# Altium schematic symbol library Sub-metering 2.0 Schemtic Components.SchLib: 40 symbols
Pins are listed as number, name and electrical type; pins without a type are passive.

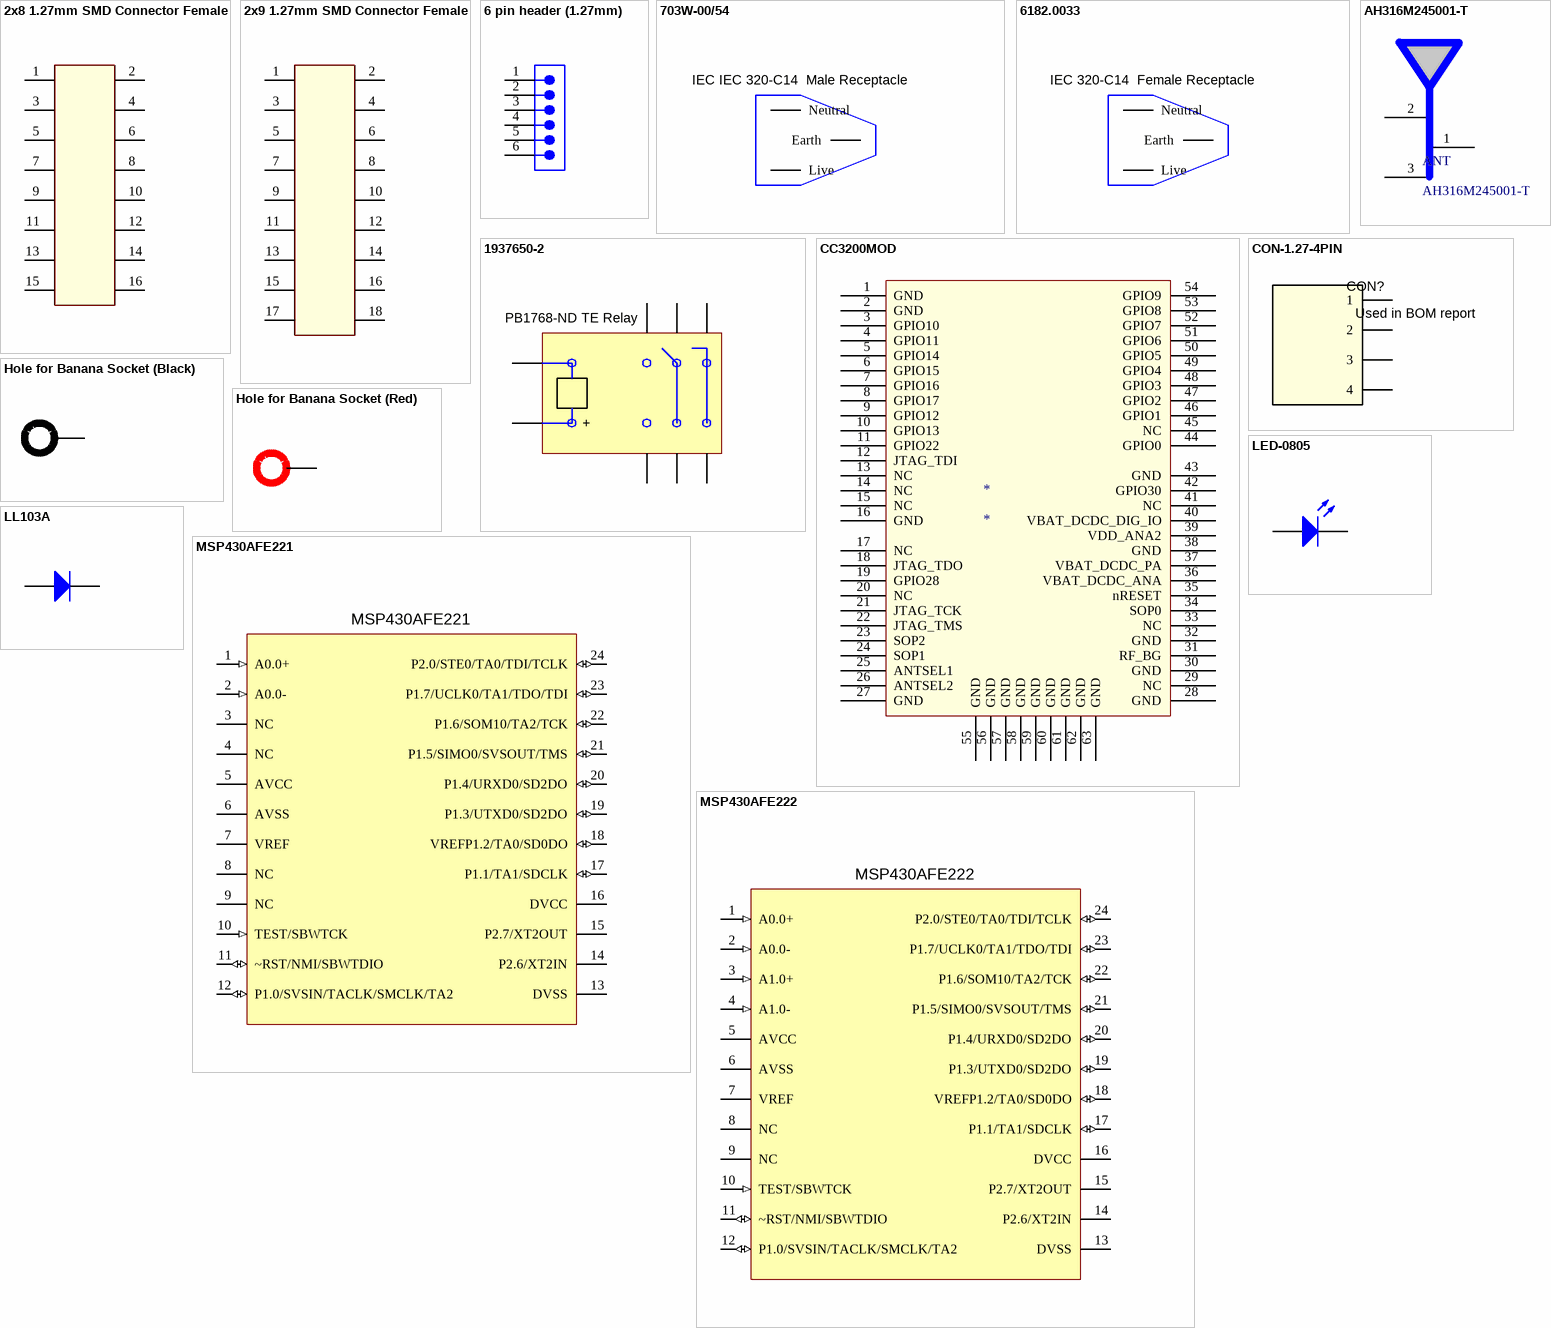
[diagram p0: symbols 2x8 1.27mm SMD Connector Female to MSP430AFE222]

## 2x8 1.27mm SMD Connector Female
designator U?, comment Used in BOM report
SymbolVersion: use current date i.e. 2008-05-20; SymbolCreator: Use LDAP id; CompType: Used in some BOM reports.  Useful for finding later.; U/M: EA, IN, or GM
footprint 2X8 1.27mm PITCH CONNECTOR FEMALE
pins: 1, 2, 3, 4, 5, 6, 7, 8, 9, 10, 11, 12, 13, 14, 15, 16

## 2x9 1.27mm SMD Connector Female
designator U?, comment Used in BOM report
SymbolVersion: use current date i.e. 2008-05-20; SymbolCreator: Use LDAP id; CompType: Used in some BOM reports.  Useful for finding later.; U/M: EA, IN, or GM
footprint 2X9 1.27mm PITCH CONNECTOR FEMALE
pins: 1, 2, 3, 4, 5, 6, 7, 8, 9, 10, 11, 12, 13, 14, 15, 16, 17, 18

## 6 pin header (1.27mm)
designator U?, comment Used in BOM report
SymbolVersion: use current date i.e. 2008-05-20; SymbolCreator: Use LDAP id; CompType: Used in some BOM reports.  Useful for finding later.; U/M: EA, IN, or GM
footprint 6-pin header (1.27mm) (6 pin header 1.27mm)
pins: 1, 2, 3, 4, 5, 6

## 703W-00/54
designator SOC?
CONN AC RECEPT 9MM R/A FLAT PCB; Manufacturer: Qualtek; SymbolVersion: use current date i.e. 2008-05-20; SymbolCreator: Use a-id; CompType: Used in some BOM reports.  Useful for finding later.; U/M: EA, IN, or GM; Connector Style: IEC 320-C14; Connector Type: Receptacle, Male Pins; Irms: 10A; Voltage: 250V; Number of Positions: 3; Fuse Drawer: Drawer Not Required
footprint 703W-00/54 (IEC 320-C14 , Receptacle, Male Pins)
pins: 1 Earth, 2 Neutral, 3 Live

## 6182.0033
designator SOC?
MODULE PWR OUTLET F SCREW-ON PCB; Manufacturer: Schurter Inc; SymbolVersion: use current date i.e. 2008-05-20; SymbolCreator: Use a-id; CompType: Used in some BOM reports.  Useful for finding later.; U/M: EA, IN, or GM; Connector Style: IEC 320-C13; Connector Type: Receptacle, Female Sockets; Irms: 15A; Voltage: 250V; Number of Positions: 3; Fuse Drawer: Drawer Not Required
footprint 486-1343-ND
pins: 1 Earth, 2 Neutral, 3 Live

## 1937650-2
designator REL?, comment RTX3-1AT-B005
RELAY GEN PURPOSE SPST 16A 5V; Manufacturer: TE Electronics; SymbolVersion: use current date i.e. 2008-05-20; SymbolCreator: Use a-id; CompType: Used in some BOM reports.  Useful for finding later.; U/M: EA, IN, or GM; Relay Type: General Purpose; Coil Type: Latching, Single Coil; Coil Current: 130mA; Coil Voltage: 5VDC; Contact Form: SPST-NO (1 Form A); Switching Voltage: 250VAC - Nom; Turn On Voltage (Max): 3.75 VDC; Coil Power: 650 mW; Coil Resistance: 38 Ohms
footprint TE RELAY TYPE A (TE Relay type A footprint)
pins: 1, 2, 3, 4, 5, 6, 7, 8

## AH316M245001-T
designator ANT
Manufacturer: Taiyo Yuden; Value: 2.45-GHz Ant
footprint AH316M
pins: 1, 2, 3

## CC3200MOD
designator *
footprint CC3200MOD
pins: 1 GND, 2 GND, 3 GPIO10, 4 GPIO11, 5 GPIO14, 6 GPIO15, 7 GPIO16, 8 GPIO17, 9 GPIO12, 10 GPIO13, 11 GPIO22, 12 JTAG_TDI, 13 NC, 14 NC, 15 NC, 16 GND, 17 NC, 18 JTAG_TDO, 19 GPIO28, 20 NC, 21 JTAG_TCK, 22 JTAG_TMS, 23 SOP2, 24 SOP1, 25 ANTSEL1, 26 ANTSEL2, 27 GND, 28 GND, 29 NC, 30 GND, 31 RF_BG, 32 GND, 33 NC, 34 SOP0, 35 nRESET, 36 VBAT_DCDC_ANA, 37 VBAT_DCDC_PA, 38 GND, 39 VDD_ANA2, 40 VBAT_DCDC_DIG_IO, 41 NC, 42 GPIO30, 43 GND, 44 GPIO0, 45 NC, 46 GPIO1, 47 GPIO2, 48 GPIO3, 49 GPIO4, 50 GPIO5, 51 GPIO6, 52 GPIO7, 53 GPIO8, 54 GPIO9, 55 GND, 56 GND, 57 GND, 58 GND, 59 GND, 60 GND, 61 GND, 62 GND, 63 GND

## CON-1.27-4PIN
designator CON?, comment Used in BOM report
SymbolVersion: use current date i.e. 2008-05-20; SymbolCreator: Use a-id; CompType: Used in some BOM reports.  Useful for finding later.; U/M: EA, IN, or GM
footprint CON-1.27-4PIN (1.27mm connector 4 pin)
pins: 1, 2, 3, 4

## Hole for Banana Socket (Black)
designator J?, comment Used in BOM report
SymbolVersion: use current date i.e. 2008-05-20; SymbolCreator: Use LDAP id; CompType: Used in some BOM reports.  Useful for finding later.; U/M: EA, IN, or GM
footprint Hole for Banana Socket
pins: 1

## Hole for Banana Socket (Red)
designator J?, comment Used in BOM report
SymbolVersion: use current date i.e. 2008-05-20; SymbolCreator: Use LDAP id; CompType: Used in some BOM reports.  Useful for finding later.; U/M: EA, IN, or GM
footprint Hole for Banana Socket
pins: 1

## LED-0805
designator U?, comment Used in BOM report
SymbolVersion: use current date i.e. 2008-05-20; SymbolCreator: Use LDAP id; CompType: Used in some BOM reports.  Useful for finding later.; U/M: EA, IN, or GM
footprint 0805-LED
pins: 1 A, 2 K

## LL103A
designator D?
Manufacturer: Used in BOM report; SymbolVersion: use current date i.e. 2008-05-20; SymbolCreator: Use LDAP id; CompType: Used in some BOM reports.  Useful for finding later.; U/M: EA, IN, or GM
footprint SOD-80 (VISHAY)
pins: 1 A, 2 K

## MSP430AFE221
designator U?
Manufacturer: Texas Instruments; SymbolVersion: use current date i.e. 2008-05-20; SymbolCreator: Use LDAP id; CompType: Used in some BOM reports.  Useful for finding later.; U/M: EA, IN, or GM
footprint R-PDSO-G24
footprint TSSOP-24 (TSSOP-24 (IPW))
pins: 1 A0.0+ (in), 2 A0.0- (in), 3 NC, 4 NC, 5 AVCC (power), 6 AVSS (power), 7 VREF, 8 NC, 9 NC, 10 TEST/SBWTCK (in), 11 ~RST/NMI/SBWTDIO (io), 12 P1.0/SVSIN/TACLK/SMCLK/TA2 (io), 13 DVSS (power), 14 P2.6/XT2IN, 15 P2.7/XT2OUT, 16 DVCC (power), 17 P1.1/TA1/SDCLK (io), 18 VREFP1.2/TA0/SD0DO (io), 19 P1.3/UTXD0/SD2DO (io), 20 P1.4/URXD0/SD2DO (io), 21 P1.5/SIMO0/SVSOUT/TMS (io), 22 P1.6/SOM10/TA2/TCK (io), 23 P1.7/UCLK0/TA1/TDO/TDI (io), 24 P2.0/STE0/TA0/TDI/TCLK (io)

## MSP430AFE222
designator U?
Manufacturer: Texas Instruments; SymbolVersion: use current date i.e. 2008-05-20; SymbolCreator: Use LDAP id; CompType: Used in some BOM reports.  Useful for finding later.; U/M: EA, IN, or GM
footprint R-PDSO-G24
footprint TSSOP-24 (TSSOP-24 (IPW))
pins: 1 A0.0+ (in), 2 A0.0- (in), 3 A1.0+ (in), 4 A1.0- (in), 5 AVCC (power), 6 AVSS (power), 7 VREF, 8 NC, 9 NC, 10 TEST/SBWTCK (in), 11 ~RST/NMI/SBWTDIO (io), 12 P1.0/SVSIN/TACLK/SMCLK/TA2 (io), 13 DVSS (power), 14 P2.6/XT2IN, 15 P2.7/XT2OUT, 16 DVCC (power), 17 P1.1/TA1/SDCLK (io), 18 VREFP1.2/TA0/SD0DO (io), 19 P1.3/UTXD0/SD2DO (io), 20 P1.4/URXD0/SD2DO (io), 21 P1.5/SIMO0/SVSOUT/TMS (io), 22 P1.6/SOM10/TA2/TCK (io), 23 P1.7/UCLK0/TA1/TDO/TDI (io), 24 P2.0/STE0/TA0/TDI/TCLK (io)

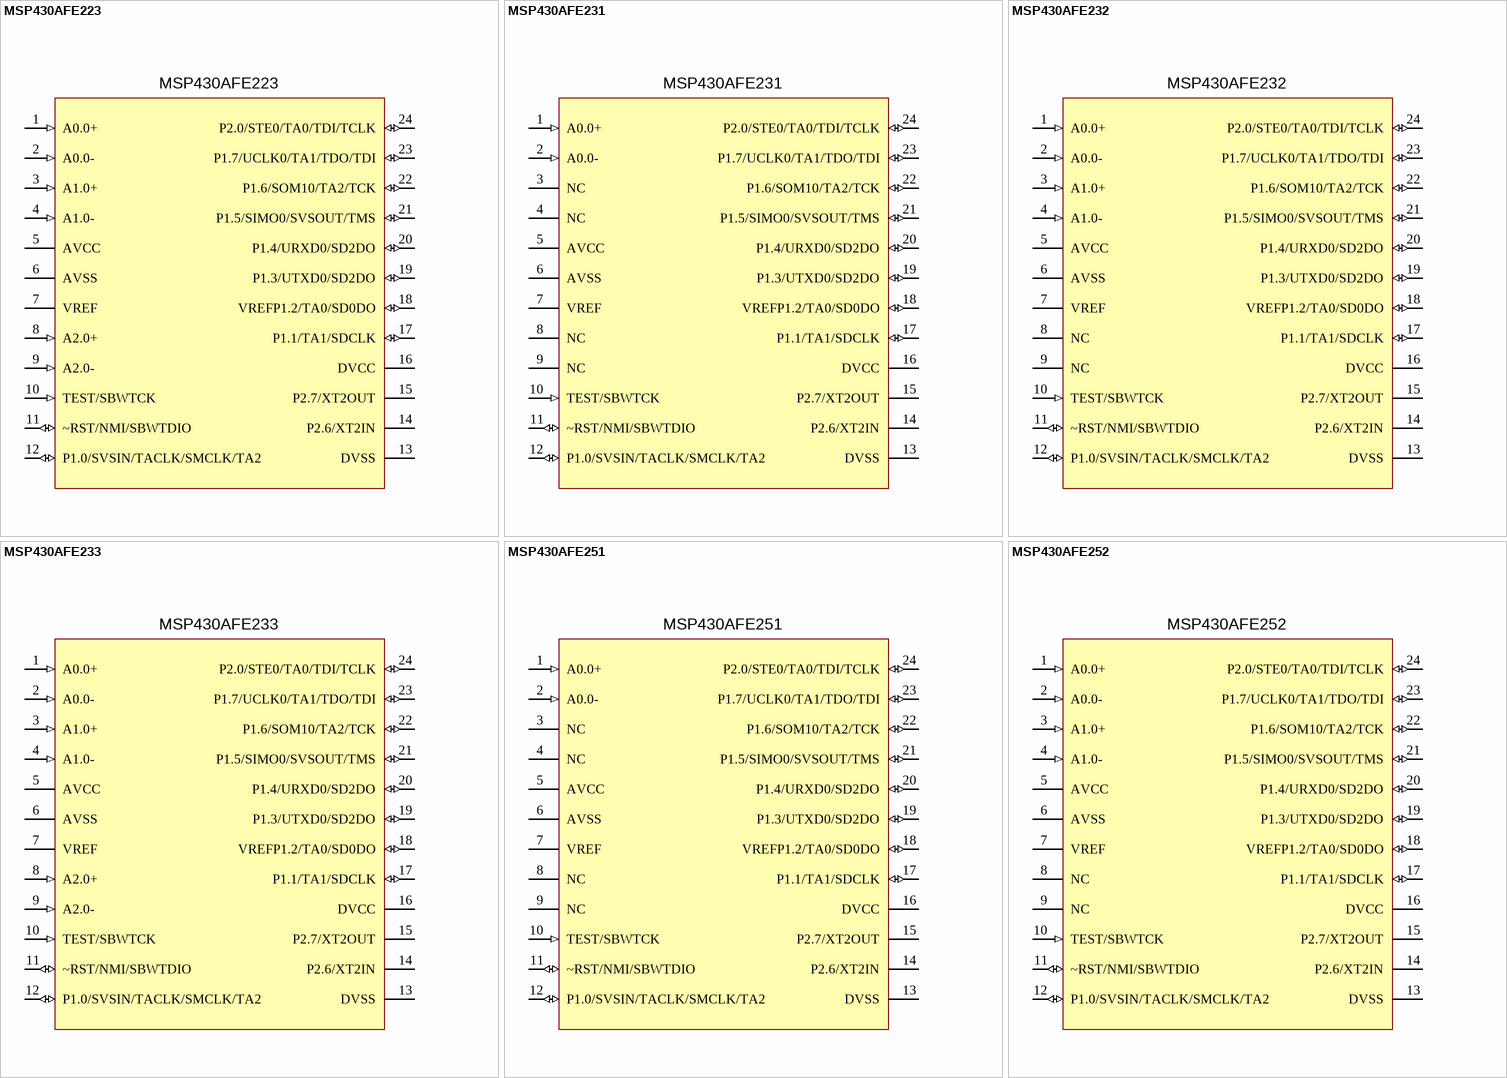
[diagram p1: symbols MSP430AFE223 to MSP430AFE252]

## MSP430AFE223
designator U?
Manufacturer: Texas Instruments; SymbolVersion: use current date i.e. 2008-05-20; SymbolCreator: Use LDAP id; CompType: Used in some BOM reports.  Useful for finding later.; U/M: EA, IN, or GM
footprint R-PDSO-G24
footprint TSSOP-24 (TSSOP-24 (IPW))
pins: 1 A0.0+ (in), 2 A0.0- (in), 3 A1.0+ (in), 4 A1.0- (in), 5 AVCC (power), 6 AVSS (power), 7 VREF, 8 A2.0+ (in), 9 A2.0- (in), 10 TEST/SBWTCK (in), 11 ~RST/NMI/SBWTDIO (io), 12 P1.0/SVSIN/TACLK/SMCLK/TA2 (io), 13 DVSS (power), 14 P2.6/XT2IN, 15 P2.7/XT2OUT, 16 DVCC (power), 17 P1.1/TA1/SDCLK (io), 18 VREFP1.2/TA0/SD0DO (io), 19 P1.3/UTXD0/SD2DO (io), 20 P1.4/URXD0/SD2DO (io), 21 P1.5/SIMO0/SVSOUT/TMS (io), 22 P1.6/SOM10/TA2/TCK (io), 23 P1.7/UCLK0/TA1/TDO/TDI (io), 24 P2.0/STE0/TA0/TDI/TCLK (io)

## MSP430AFE231
designator U?
Manufacturer: Texas Instruments; SymbolVersion: use current date i.e. 2008-05-20; SymbolCreator: Use LDAP id; CompType: Used in some BOM reports.  Useful for finding later.; U/M: EA, IN, or GM
footprint R-PDSO-G24
footprint TSSOP-24 (TSSOP-24 (IPW))
pins: 1 A0.0+ (in), 2 A0.0- (in), 3 NC, 4 NC, 5 AVCC (power), 6 AVSS (power), 7 VREF, 8 NC, 9 NC, 10 TEST/SBWTCK (in), 11 ~RST/NMI/SBWTDIO (io), 12 P1.0/SVSIN/TACLK/SMCLK/TA2 (io), 13 DVSS (power), 14 P2.6/XT2IN, 15 P2.7/XT2OUT, 16 DVCC (power), 17 P1.1/TA1/SDCLK (io), 18 VREFP1.2/TA0/SD0DO (io), 19 P1.3/UTXD0/SD2DO (io), 20 P1.4/URXD0/SD2DO (io), 21 P1.5/SIMO0/SVSOUT/TMS (io), 22 P1.6/SOM10/TA2/TCK (io), 23 P1.7/UCLK0/TA1/TDO/TDI (io), 24 P2.0/STE0/TA0/TDI/TCLK (io)

## MSP430AFE232
designator U?
Manufacturer: Texas Instruments; SymbolVersion: use current date i.e. 2008-05-20; SymbolCreator: Use LDAP id; CompType: Used in some BOM reports.  Useful for finding later.; U/M: EA, IN, or GM
footprint R-PDSO-G24
footprint TSSOP-24 (TSSOP-24 (IPW))
pins: 1 A0.0+ (in), 2 A0.0- (in), 3 A1.0+ (in), 4 A1.0- (in), 5 AVCC (power), 6 AVSS (power), 7 VREF, 8 NC, 9 NC, 10 TEST/SBWTCK (in), 11 ~RST/NMI/SBWTDIO (io), 12 P1.0/SVSIN/TACLK/SMCLK/TA2 (io), 13 DVSS (power), 14 P2.6/XT2IN, 15 P2.7/XT2OUT, 16 DVCC (power), 17 P1.1/TA1/SDCLK (io), 18 VREFP1.2/TA0/SD0DO (io), 19 P1.3/UTXD0/SD2DO (io), 20 P1.4/URXD0/SD2DO (io), 21 P1.5/SIMO0/SVSOUT/TMS (io), 22 P1.6/SOM10/TA2/TCK (io), 23 P1.7/UCLK0/TA1/TDO/TDI (io), 24 P2.0/STE0/TA0/TDI/TCLK (io)

## MSP430AFE233
designator U?
Manufacturer: Texas Instruments; SymbolVersion: use current date i.e. 2008-05-20; SymbolCreator: Use LDAP id; CompType: Used in some BOM reports.  Useful for finding later.; U/M: EA, IN, or GM
footprint R-PDSO-G24
footprint TSSOP-24 (TSSOP-24 (IPW))
pins: 1 A0.0+ (in), 2 A0.0- (in), 3 A1.0+ (in), 4 A1.0- (in), 5 AVCC (power), 6 AVSS (power), 7 VREF, 8 A2.0+ (in), 9 A2.0- (in), 10 TEST/SBWTCK (in), 11 ~RST/NMI/SBWTDIO (io), 12 P1.0/SVSIN/TACLK/SMCLK/TA2 (io), 13 DVSS (power), 14 P2.6/XT2IN, 15 P2.7/XT2OUT, 16 DVCC (power), 17 P1.1/TA1/SDCLK (io), 18 VREFP1.2/TA0/SD0DO (io), 19 P1.3/UTXD0/SD2DO (io), 20 P1.4/URXD0/SD2DO (io), 21 P1.5/SIMO0/SVSOUT/TMS (io), 22 P1.6/SOM10/TA2/TCK (io), 23 P1.7/UCLK0/TA1/TDO/TDI (io), 24 P2.0/STE0/TA0/TDI/TCLK (io)

## MSP430AFE251
designator U?
Manufacturer: Texas Instruments; SymbolVersion: use current date i.e. 2008-05-20; SymbolCreator: Mars Leung; CompType: Used in some BOM reports.  Useful for finding later.; U/M: EA, IN, or GM
footprint R-PDSO-G24
footprint TSSOP-24 (TSSOP-24 (IPW))
pins: 1 A0.0+ (in), 2 A0.0- (in), 3 NC, 4 NC, 5 AVCC (power), 6 AVSS (power), 7 VREF, 8 NC, 9 NC, 10 TEST/SBWTCK (in), 11 ~RST/NMI/SBWTDIO (io), 12 P1.0/SVSIN/TACLK/SMCLK/TA2 (io), 13 DVSS (power), 14 P2.6/XT2IN, 15 P2.7/XT2OUT, 16 DVCC (power), 17 P1.1/TA1/SDCLK (io), 18 VREFP1.2/TA0/SD0DO (io), 19 P1.3/UTXD0/SD2DO (io), 20 P1.4/URXD0/SD2DO (io), 21 P1.5/SIMO0/SVSOUT/TMS (io), 22 P1.6/SOM10/TA2/TCK (io), 23 P1.7/UCLK0/TA1/TDO/TDI (io), 24 P2.0/STE0/TA0/TDI/TCLK (io)

## MSP430AFE252
designator U?
Manufacturer: Texas Instruments; SymbolVersion: use current date i.e. 2008-05-20; SymbolCreator: Mars Leung; CompType: Used in some BOM reports.  Useful for finding later.; U/M: EA, IN, or GM
footprint R-PDSO-G24
footprint TSSOP-24 (TSSOP-24 (IPW))
pins: 1 A0.0+ (in), 2 A0.0- (in), 3 A1.0+ (in), 4 A1.0- (in), 5 AVCC (power), 6 AVSS (power), 7 VREF, 8 NC, 9 NC, 10 TEST/SBWTCK (in), 11 ~RST/NMI/SBWTDIO (io), 12 P1.0/SVSIN/TACLK/SMCLK/TA2 (io), 13 DVSS (power), 14 P2.6/XT2IN, 15 P2.7/XT2OUT, 16 DVCC (power), 17 P1.1/TA1/SDCLK (io), 18 VREFP1.2/TA0/SD0DO (io), 19 P1.3/UTXD0/SD2DO (io), 20 P1.4/URXD0/SD2DO (io), 21 P1.5/SIMO0/SVSOUT/TMS (io), 22 P1.6/SOM10/TA2/TCK (io), 23 P1.7/UCLK0/TA1/TDO/TDI (io), 24 P2.0/STE0/TA0/TDI/TCLK (io)

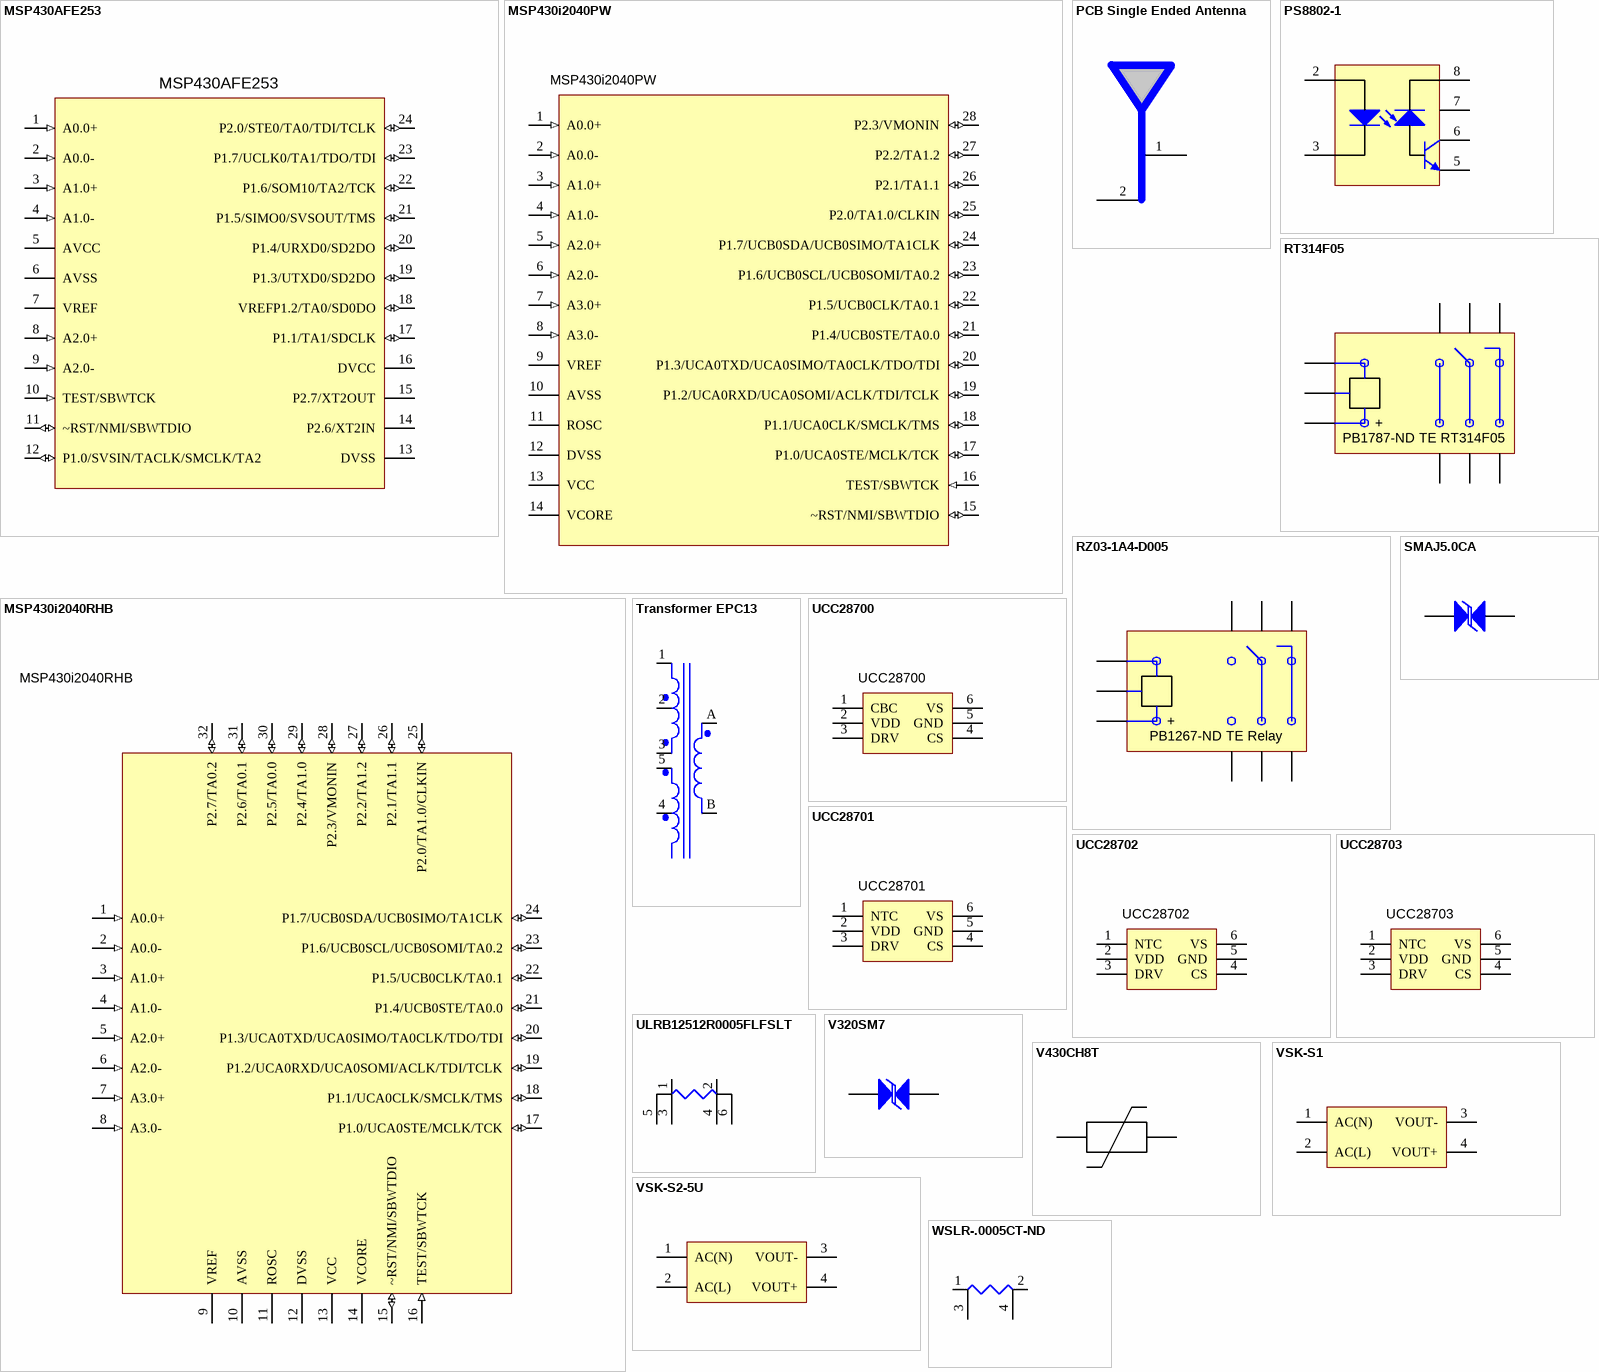
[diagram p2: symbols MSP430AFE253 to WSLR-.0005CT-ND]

## MSP430AFE253
designator U?
Manufacturer: Texas Instruments; SymbolVersion: use current date i.e. 2008-05-20; SymbolCreator: Mars Leung; CompType: Used in some BOM reports.  Useful for finding later.; U/M: EA, IN, or GM
footprint R-PDSO-G24
footprint TSSOP-24 (TSSOP-24 (IPW))
footprint TSSO8X6-G24/D7.9
pins: 1 A0.0+ (in), 2 A0.0- (in), 3 A1.0+ (in), 4 A1.0- (in), 5 AVCC (power), 6 AVSS (power), 7 VREF, 8 A2.0+ (in), 9 A2.0- (in), 10 TEST/SBWTCK (in), 11 ~RST/NMI/SBWTDIO (io), 12 P1.0/SVSIN/TACLK/SMCLK/TA2 (io), 13 DVSS (power), 14 P2.6/XT2IN, 15 P2.7/XT2OUT, 16 DVCC (power), 17 P1.1/TA1/SDCLK (io), 18 VREFP1.2/TA0/SD0DO (io), 19 P1.3/UTXD0/SD2DO (io), 20 P1.4/URXD0/SD2DO (io), 21 P1.5/SIMO0/SVSOUT/TMS (io), 22 P1.6/SOM10/TA2/TCK (io), 23 P1.7/UCLK0/TA1/TDO/TDI (io), 24 P2.0/STE0/TA0/TDI/TCLK (io)

## MSP430i2040PW
designator U?
Manufacturer: Texas Instruments; SymbolVersion: use current date i.e. 2008-05-20; SymbolCreator: Use LDAP id; CompType: Used in some BOM reports.  Useful for finding later.; U/M: EA, IN, or GM
footprint TSSO10x6-G28 (Shrink Small Outline; 28 Leads; Body Width 4.4 mm; Pitch 0.65 mm)
pins: 1 A0.0+ (in), 2 A0.0- (in), 3 A1.0+ (in), 4 A1.0- (in), 5 A2.0+ (in), 6 A2.0- (in), 7 A3.0+ (in), 8 A3.0- (in), 9 VREF, 10 AVSS (power), 11 ROSC, 12 DVSS (power), 13 VCC (power), 14 VCORE, 15 ~RST/NMI/SBWTDIO (io), 16 TEST/SBWTCK (in), 17 P1.0/UCA0STE/MCLK/TCK (io), 18 P1.1/UCA0CLK/SMCLK/TMS (io), 19 P1.2/UCA0RXD/UCA0SOMI/ACLK/TDI/TCLK (io), 20 P1.3/UCA0TXD/UCA0SIMO/TA0CLK/TDO/TDI (io), 21 P1.4/UCB0STE/TA0.0 (io), 22 P1.5/UCB0CLK/TA0.1 (io), 23 P1.6/UCB0SCL/UCB0SOMI/TA0.2 (io), 24 P1.7/UCB0SDA/UCB0SIMO/TA1CLK (io), 25 P2.0/TA1.0/CLKIN (io), 26 P2.1/TA1.1 (io), 27 P2.2/TA1.2 (io), 28 P2.3/VMONIN (io)

## MSP430i2040RHB
designator U?
Manufacturer: Texas Instruments; SymbolVersion: use current date i.e. 2008-05-20; SymbolCreator: Use LDAP id; CompType: Used in some BOM reports.  Useful for finding later.; U/M: EA, IN, or GM
footprint QFN-32_V (QFN, 32-Leads, Body 5x5mm, Pitch 0.5mm, Thermal Pad 3.3x3.3mm, Silicon Labs Recommended)
pins: 1 A0.0+ (in), 2 A0.0- (in), 3 A1.0+ (in), 4 A1.0- (in), 5 A2.0+ (in), 6 A2.0- (in), 7 A3.0+ (in), 8 A3.0- (in), 9 VREF, 10 AVSS (power), 11 ROSC, 12 DVSS (power), 13 VCC (power), 14 VCORE, 15 ~RST/NMI/SBWTDIO (io), 16 TEST/SBWTCK (in), 17 P1.0/UCA0STE/MCLK/TCK (io), 18 P1.1/UCA0CLK/SMCLK/TMS (io), 19 P1.2/UCA0RXD/UCA0SOMI/ACLK/TDI/TCLK (io), 20 P1.3/UCA0TXD/UCA0SIMO/TA0CLK/TDO/TDI (io), 21 P1.4/UCB0STE/TA0.0 (io), 22 P1.5/UCB0CLK/TA0.1 (io), 23 P1.6/UCB0SCL/UCB0SOMI/TA0.2 (io), 24 P1.7/UCB0SDA/UCB0SIMO/TA1CLK (io), 25 P2.0/TA1.0/CLKIN (io), 26 P2.1/TA1.1 (io), 27 P2.2/TA1.2 (io), 28 P2.3/VMONIN (io), 29 P2.4/TA1.0 (io), 30 P2.5/TA0.0 (io), 31 P2.6/TA0.1 (io), 32 P2.7/TA0.2 (io)

## PCB Single Ended Antenna
designator ANT?, comment N/A  (value not drawn)
CompType: PCB Antenna
footprint 2.4G PCB ANT (2.4G PCb Single Ended Antenna)
pins: 1, 2

## PS8802-1
designator U?
Manufacturer: Used in BOM report; SymbolVersion: use current date i.e. 2008-05-20; SymbolCreator: Use LDAP id; CompType: Used in some BOM reports.  Useful for finding later.; U/M: EA, IN, or GM
footprint SO-8 (Footprint not found)
pins: 1 hidden, 2, 3, 4 hidden, 5, 6, 7, 8

## RT314F05
designator REL?
General Purpose Relays 5V 16A 1CO THT POWER RELAY; Manufacturer: TE Electronics; SymbolVersion: use current date i.e. 2008-05-20; SymbolCreator: Use a-id; CompType: Used in some BOM reports.  Useful for finding later.; U/M: EA, IN, or GM; Coil Type: Bistable; Contact Form: 1 Form C (SPDT-BM); Contact Termination: Pin; Power Consumption: 600 mW; Brand: TE Connectivity / Schrack; Coil Resistance: 42 Ohms; Switching Voltage: 400 VAC
footprint TE RELAY TYPE A (TE Relay type A footprint)
pins: 1, 2, 3, 4, 5, 6, 7, 8, 9

## RZ03-1A4-D005
designator REL?, comment RZ031A4D005
RELAY GEN PURPOSE SPST 16A 5V; Manufacturer: TE Electronics; SymbolVersion: use current date i.e. 2008-05-20; SymbolCreator: Use a-id; CompType: Used in some BOM reports.  Useful for finding later.; U/M: EA, IN, or GM; Relay Type: General Purpose; Coil Type: Non Latching; Coil Current: 84mA; Coil Voltage: 5VDC; Contact Form: SPST-NO (1 Form A); Switching Voltage: 400VAC - Max; Turn On Voltage (Max): 3.5 VDC; Turn Off Voltage (Min): 0.5 VDC; Operate Time: 8ms; Release Time: 6ms; Coil Power: 420 mW; Coil Resistance: 60 Ohms
footprint TE RELAY TYPE A (TE Relay type A footprint)
pins: 1, 2 A1, 3, 4, 5, 6, 7, 8, 9

## SMAJ5.0CA
designator D?
Manufacturer: Used in BOM report; SymbolVersion: use current date i.e. 2008-05-20; SymbolCreator: Use LDAP id; CompType: Used in some BOM reports.  Useful for finding later.; U/M: EA, IN, or GM
footprint DSO-C2/X1.8 (DO-214-AC/SMA; 2 C-Bend Leads; Body 5 x 2.7 mm, inc. leads (LxW))
pins: 1, 2

## Transformer EPC13
designator T?
SymbolVersion: use current date i.e. 2008-05-20; SymbolCreator: Use LDAP id; CompType: Transformer; U/M: EA, IN, or GM
pins: 1 Pri, 2 PriCT, 3 Pri+, 4 ACT, 5 A+, A Sec+, B Sec-

## UCC28700
designator U?, comment UCC28700DBV
Manufacturer: Texas Instruments; SymbolVersion: use current date i.e. 2008-05-20; SymbolCreator: Use LDAP id; CompType: DC-DC; U/M: EA, IN, or GM
footprint MF06A_L (SOT23, 6-Leads, Body 2.9x1.6mm, Pitch 0.95mm, Lead Span 2.8mm, IPC High Density)
pins: 1 CBC, 2 VDD, 3 DRV, 4 CS, 5 GND, 6 VS

## UCC28701
designator U?, comment UCC28701DBV
Manufacturer: Texas Instruments; SymbolVersion: use current date i.e. 2008-05-20; SymbolCreator: Use LDAP id; CompType: DC-DC; U/M: EA, IN, or GM
footprint MF06A_L (SOT23, 6-Leads, Body 2.9x1.6mm, Pitch 0.95mm, Lead Span 2.8mm, IPC High Density)
pins: 1 NTC, 2 VDD, 3 DRV, 4 CS, 5 GND, 6 VS

## UCC28702
designator U?, comment UCC28702DBV
Manufacturer: Texas Instruments; SymbolVersion: use current date i.e. 2008-05-20; SymbolCreator: Use LDAP id; CompType: DC-DC; U/M: EA, IN, or GM
footprint MF06A_L (SOT23, 6-Leads, Body 2.9x1.6mm, Pitch 0.95mm, Lead Span 2.8mm, IPC High Density)
pins: 1 NTC, 2 VDD, 3 DRV, 4 CS, 5 GND, 6 VS

## UCC28703
designator U?, comment UCC28703DBV
Manufacturer: Texas Instruments; SymbolVersion: use current date i.e. 2008-05-20; SymbolCreator: Use LDAP id; CompType: DC-DC; U/M: EA, IN, or GM
footprint MF06A_L (SOT23, 6-Leads, Body 2.9x1.6mm, Pitch 0.95mm, Lead Span 2.8mm, IPC High Density)
pins: 1 NTC, 2 VDD, 3 DRV, 4 CS, 5 GND, 6 VS

## ULRB12512R0005FLFSLT
designator R?, comment Used in BOM report
Shunt Resistor; SymbolVersion: use current date i.e. 2008-05-20; SymbolCreator: Use LDAP id; CompType: Used in some BOM reports.  Useful for finding later.; U/M: EA, IN, or GM
footprint Current Sensing Pad (Current Sensing Pad for 2512)
pins: 1, 2, 3, 4, 5, 6

## V320SM7
designator U?, comment Used in BOM report
SymbolVersion: use current date i.e. 2008-05-20; SymbolCreator: Use LDAP id; CompType: Used in some BOM reports.  Useful for finding later.; U/M: EA, IN, or GM
footprint V320SM7 (SMD MOV)
pins: 1, 2

## V430CH8T
designator D?
VARISTOR 389V 250A 2-SMD; Manufacturer: Used in BOM report; SymbolVersion: use current date i.e. 2008-05-20; SymbolCreator: Use a-id; CompType: Used in some BOM reports.  Useful for finding later.; U/M: EA, IN, or GM; Number of Circuits: 1; Maximum AC Volts: 275VAC; Maximum DC Volts: 369VDC; Energy: 8.0J
footprint V430CH8T (MOV)
pins: 1, 2

## VSK-S1
designator U?, comment Used in BOM report
On board block power suppply; Manufacturer: CUN Inc; SymbolVersion: use current date i.e. 2008-05-20; SymbolCreator: Use LDAP id; CompType: Power Supply; U/M: EA, IN, or GM
footprint VSK-S1 (On board block power supply)
pins: 1 AC(N), 2 AC(L), 3 VOUT-, 4 VOUT+

## VSK-S2-5U
designator U?, comment Used in BOM report
POWER SUPPLY SWITCHING 5V 2W; SymbolVersion: use current date i.e. 2008-05-20; SymbolCreator: Use a-id; CompType: Used in some BOM reports.  Useful for finding later.; U/M: EA, IN, or GM; Number of Outputs: 1; Voltage - Input: 85 ~ 305 VAC; Current - Output (Max): 400mA; Power Supply Type: Switching (Closed Frame); Efficiency: 70%; Line Regulation: ?%; Approvals: CE, cULus
footprint VSK-S1 (On board block power supply)
pins: 1 AC(N), 2 AC(L), 3 VOUT-, 4 VOUT+

## WSLR-.0005CT-ND
designator R?
RES .0005 OHM 3W 1% 4026 SMD; Manufacturer: Used in BOM report; SymbolVersion: use current date i.e. 2008-05-20; SymbolCreator: Use a-id; CompType: Used in some BOM reports.  Useful for finding later.; U/M: EA, IN, or GM; Value: 0.0005; Tolerance_%: ?%; TempCo: ?5ppm/°C
footprint CURRENT_SENSING_PAD_A; pin to pad 3>5 4>6
pins: 1, 2, 3, 4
